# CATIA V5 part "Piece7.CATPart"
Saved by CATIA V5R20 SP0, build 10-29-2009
Part number: Piece7
Bounding box of the stored display mesh (mm): x -2 to 0, y 17.002 to 58.582, z 33.487 to 115.282
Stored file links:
  D:\Dropbox\IAO_2012\IAO_2012_815_gcordenod\gcordenod\Piece7.CATPart
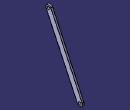
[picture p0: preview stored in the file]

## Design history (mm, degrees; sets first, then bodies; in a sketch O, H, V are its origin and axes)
Body1 (main body)
  Plane1: stored without definition
  Plane2: stored without definition
  Line1 to Line3: stored without definition
  Point1 "L": stored without definition
  Point2 "D": stored without definition
  Point3 "L": stored without definition
  Sketch1 on Plane1, origin (0, 0, 0), H (0, 1, 0), V (0, 0, 1)
    line L1 (17.2844, 111.0085) -> (52.8677, 35.2107)
    arc A1 centre (55.5834, 36.4855) radius 3 from (52.8677, 35.2107) to (58.299, 37.7604) ccw
    line L2 (58.299, 37.7604) -> (22.7156, 113.5582)
    arc A2 centre (20, 112.2834) radius 3 from (22.7156, 113.5582) to (17.2844, 111.0085) ccw
    reference projected line E1 (55.5834, 36.4855) -> (20, 112.2834) from Line2
    reference projected line E2 (55.5834, 36.4855) -> (20, 112.2834) from Line3
    reference projected point E3 (20, 112.2834) from Point1
    reference projected point E4 (55.5834, 36.4855) from Point2
    distance E2 L2 = 3
    tangency: A1 L1, L2 A1, A2 L1, A2 L2
    parallelism: L2 L1, L1 E1
    concentricity: A2 E3, E4 A1
  Pad1: profile Sketch1, direction (-1, 0, 0), length 2
  Point4 "D": stored without definition
  Sketch2 on start face of Pad1, origin (0, 20, 112.2834), H (0, 1, 0), V (0, 0, 1)
    point P1 (0, 0)
    reference projected point E1 (0, 0) from Point3
    coincidence: E1 P1
  Hole1: placed by Sketch2, at (0, 20, 112.2834) direction (-1, 0, 0), diameter 3, through (limit type 3)
  Plane3: stored without definition
  Sketch3 on start face of Pad1, origin (0, 55.5834, 36.4855), H (0, 1, 0), V (0, 0, 1)
    point P1 (0, 0)
    reference projected point E1 (0, 0) from Point4
    coincidence: E1 P1
  Hole2: placed by Sketch3, at (0, 55.5834, 36.4855) direction (-1, 0, 0), diameter 3, through (limit type 3)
